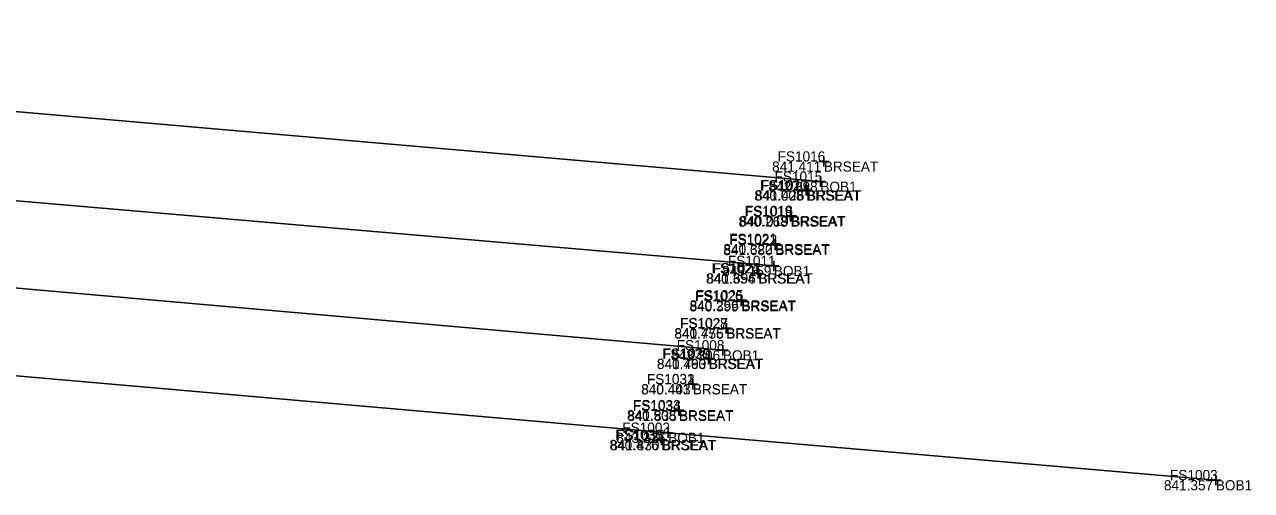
# Model space of a CAD drawing. Extents: x 1455931 to 1456172, y 560190 to 560355.
# Drawn here: x 1456051.6 to 1456172.2, y 560192.7 to 560238.5 of the extents above; entities that cross this region are included whole.
import ezdxf

# ---------------------------------------------------------------- set-up
doc = ezdxf.new("R2010")
doc.units = 0
for name, color, linetype in [('BR_X_SV_Beam_Seat', 7, 'Continuous'), ('BR_X_SV_Bottom_of_Beam', 7, 'Continuous'), ('BR_X_SV_Bottom_of_Beam_Text', 7, 'Continuous'), ('BR_X_SV_Shot_Marker', 7, 'Continuous'), ('SV_X_Shot_Marker', 7, 'Continuous')]:
    doc.layers.add(name, color=color, linetype=linetype)

msp = doc.modelspace()

# ---------------------------------------------------------------- linework, layer by layer
at = {"layer": 'BR_X_SV_Bottom_of_Beam'}
for points in [[(1455951.93, 560238.47), (1455951.93, 560238.47), (1456040.42, 560230.81), (1456129.8, 560223.03)], [(1455947.04, 560230.18), (1456035.55, 560222.47), (1456125.23, 560214.75)], [(1455942.3, 560222.35), (1456030.42, 560214.36), (1456120.23, 560206.46)], [(1455937.5, 560213.52), (1456026.06, 560206.1), (1456114.85, 560198.36), (1456168.66, 560193.7)]]:
    msp.add_lwpolyline(points, dxfattribs=at)
at = {"layer": 'BR_X_SV_Shot_Marker'}
for p, q in [((1456129.64, 560225.01), (1456130.64, 560225.01)), ((1456130.14, 560225.51), (1456130.14, 560224.51)), ((1456130.14, 560225.01), (1456130.14, 560225.01)), ((1456128.42, 560222.66), (1456128.42, 560221.66)), ((1456128.5, 560222.69), (1456128.5, 560221.69)), ((1456127.92, 560222.16), (1456128.92, 560222.16)), ((1456128, 560222.19), (1456129, 560222.19)), ((1456128.42, 560222.16), (1456128.42, 560222.16)), ((1456128.5, 560222.19), (1456128.5, 560222.19)), ((1456126.87, 560220.1), (1456126.87, 560219.1)), ((1456126.95, 560220.16), (1456126.95, 560219.16)), ((1456126.37, 560219.6), (1456127.37, 560219.6)), ((1456126.45, 560219.66), (1456127.45, 560219.66)), ((1456126.87, 560219.6), (1456126.87, 560219.6)), ((1456126.95, 560219.66), (1456126.95, 560219.66)), ((1456124.86, 560216.91), (1456125.86, 560216.91)), ((1456124.88, 560216.81), (1456125.88, 560216.81)), ((1456125.36, 560217.41), (1456125.36, 560216.41)), ((1456125.36, 560216.91), (1456125.36, 560216.91)), ((1456125.38, 560217.31), (1456125.38, 560216.31)), ((1456125.38, 560216.81), (1456125.38, 560216.81)), ((1456123.18, 560214.02), (1456124.18, 560214.02)), ((1456123.23, 560214.02), (1456124.23, 560214.02)), ((1456123.68, 560214.52), (1456123.68, 560213.52)), ((1456123.68, 560214.02), (1456123.68, 560214.02)), ((1456123.73, 560214.52), (1456123.73, 560213.52)), ((1456123.73, 560214.02), (1456123.73, 560214.02)), ((1456122.02, 560211.78), (1456122.02, 560210.78)), ((1456122.07, 560211.87), (1456122.07, 560210.87)), ((1456121.52, 560211.28), (1456122.52, 560211.28)), ((1456121.57, 560211.37), (1456122.57, 560211.37)), ((1456122.02, 560211.28), (1456122.02, 560211.28)), ((1456122.07, 560211.37), (1456122.07, 560211.37)), ((1456120.54, 560209.1), (1456120.54, 560208.1)), ((1456120.57, 560209.14), (1456120.57, 560208.14)), ((1456120.04, 560208.6), (1456121.04, 560208.6)), ((1456120.07, 560208.64), (1456121.07, 560208.64)), ((1456120.54, 560208.6), (1456120.54, 560208.6)), ((1456120.57, 560208.64), (1456120.57, 560208.64)), ((1456118.3, 560205.61), (1456119.3, 560205.61)), ((1456118.36, 560205.64), (1456119.36, 560205.64)), ((1456118.8, 560206.11), (1456118.8, 560205.11)), ((1456118.8, 560205.61), (1456118.8, 560205.61)), ((1456118.86, 560206.14), (1456118.86, 560205.14)), ((1456118.86, 560205.64), (1456118.86, 560205.64)), ((1456116.77, 560203.14), (1456117.77, 560203.14)), ((1456116.77, 560203.12), (1456117.77, 560203.12)), ((1456117.27, 560203.64), (1456117.27, 560202.64)), ((1456117.27, 560203.62), (1456117.27, 560202.62)), ((1456117.27, 560203.14), (1456117.27, 560203.14)), ((1456117.27, 560203.12), (1456117.27, 560203.12)), ((1456115.4, 560200.58), (1456116.4, 560200.58)), ((1456115.9, 560201.08), (1456115.9, 560200.08)), ((1456115.9, 560200.58), (1456115.9, 560200.58)), ((1456115.92, 560201.01), (1456115.92, 560200.01)), ((1456115.42, 560200.51), (1456116.42, 560200.51)), ((1456115.92, 560200.51), (1456115.92, 560200.51)), ((1456114.18, 560198.16), (1456114.18, 560197.16)), ((1456113.68, 560197.66), (1456114.68, 560197.66)), ((1456113.76, 560197.63), (1456114.76, 560197.63)), ((1456114.18, 560197.66), (1456114.18, 560197.66)), ((1456114.26, 560198.13), (1456114.26, 560197.13)), ((1456114.26, 560197.63), (1456114.26, 560197.63))]:
    msp.add_line(p, q, dxfattribs=at)
at = {"layer": 'SV_X_Shot_Marker'}
for p, q in [((1456129.8, 560223.53), (1456129.8, 560222.53)), ((1456129.3, 560223.03), (1456130.3, 560223.03)), ((1456129.8, 560223.03), (1456129.8, 560223.03)), ((1456125.23, 560215.25), (1456125.23, 560214.25)), ((1456124.73, 560214.75), (1456125.73, 560214.75)), ((1456125.23, 560214.75), (1456125.23, 560214.75)), ((1456120.23, 560206.96), (1456120.23, 560205.96)), ((1456119.73, 560206.46), (1456120.73, 560206.46)), ((1456120.23, 560206.46), (1456120.23, 560206.46)), ((1456114.35, 560198.36), (1456115.35, 560198.36)), ((1456114.85, 560198.86), (1456114.85, 560197.86)), ((1456114.85, 560198.36), (1456114.85, 560198.36)), ((1456168.16, 560193.7), (1456169.16, 560193.7)), ((1456168.66, 560194.2), (1456168.66, 560193.2)), ((1456168.66, 560193.7), (1456168.66, 560193.7))]:
    msp.add_line(p, q, dxfattribs=at)

# ---------------------------------------------------------------- texts
at = {"layer": 'BR_X_SV_Beam_Seat'}
for s, p in [('FS1016', (1456125.6, 560225.01)), ('841.411', (1456125.06, 560224.01)), ('BRSEAT', (1456130.14, 560224.01)), ('FS1020', (1456123.87, 560222.16)), ('FS1017', (1456123.97, 560222.19)), ('840.008', (1456123.31, 560221.16)), ('841.426', (1456123.39, 560221.19)), ('BRSEAT', (1456128.42, 560221.16)), ('BRSEAT', (1456128.5, 560221.19)), ('FS1019', (1456122.35, 560219.6)), ('FS1018', (1456122.41, 560219.66)), ('840.268', (1456121.76, 560218.6)), ('840.019', (1456121.86, 560218.66)), ('BRSEAT', (1456126.87, 560218.6)), ('BRSEAT', (1456126.95, 560218.66)), ('FS1021', (1456120.84, 560216.91)), ('FS1022', (1456120.87, 560216.81)), ('841.680', (1456120.27, 560215.81)), ('840.322', (1456120.28, 560215.91)), ('BRSEAT', (1456125.36, 560215.91)), ('BRSEAT', (1456125.38, 560215.81)), ('FS1024', (1456119.12, 560214.02)), ('FS1023', (1456119.23, 560214.02)), ('840.354', (1456118.56, 560213.02)), ('841.696', (1456118.62, 560213.02)), ('BRSEAT', (1456123.68, 560213.02)), ('BRSEAT', (1456123.73, 560213.02)), ('FS1026', (1456117.48, 560211.28)), ('FS1025', (1456117.56, 560211.37)), ('840.399', (1456116.94, 560210.28)), ('840.256', (1456116.96, 560210.37)), ('BRSEAT', (1456122.02, 560210.28)), ('BRSEAT', (1456122.07, 560210.37)), ('FS1028', (1456116, 560208.6)), ('FS1027', (1456116.04, 560208.64)), ('840.476', (1456115.46, 560207.64)), ('841.755', (1456115.47, 560207.6)), ('BRSEAT', (1456120.54, 560207.6)), ('BRSEAT', (1456120.57, 560207.64)), ('FS1030', (1456114.25, 560205.61)), ('FS1029', (1456114.34, 560205.64)), ('840.463', (1456113.74, 560204.61)), ('841.790', (1456113.74, 560204.64)), ('BRSEAT', (1456118.8, 560204.61)), ('BRSEAT', (1456118.86, 560204.64)), ('840.441', (1456112.19, 560202.12)), ('840.403', (1456112.21, 560202.14)), ('FS1031', (1456112.76, 560203.14)), ('FS1032', (1456112.76, 560203.12)), ('BRSEAT', (1456117.27, 560202.14)), ('BRSEAT', (1456117.27, 560202.12)), ('840.508', (1456110.8, 560199.58)), ('FS1034', (1456111.37, 560200.51)), ('FS1033', (1456111.4, 560200.58)), ('BRSEAT', (1456115.9, 560199.58)), ('841.835', (1456110.85, 560199.51)), ('BRSEAT', (1456115.92, 560199.51)), ('FS1036', (1456109.64, 560197.66)), ('FS1035', (1456109.75, 560197.63)), ('840.476', (1456109.08, 560196.66)), ('841.830', (1456109.15, 560196.63)), ('BRSEAT', (1456114.18, 560196.66)), ('BRSEAT', (1456114.26, 560196.63))]:
    msp.add_text(s, height=1, dxfattribs=at).set_placement(p)
at = {"layer": 'BR_X_SV_Bottom_of_Beam_Text'}
for s, p in [('FS1015', (1456125.3, 560223.03)), ('842.898', (1456124.7, 560222.03)), ('BOB1', (1456129.8, 560222.03)), ('FS1011', (1456120.72, 560214.75)), ('843.159', (1456120.15, 560213.75)), ('BOB1', (1456125.23, 560213.75)), ('FS1008', (1456115.69, 560206.46)), ('843.306', (1456115.12, 560205.46)), ('BOB1', (1456120.23, 560205.46)), ('FS1002', (1456110.34, 560198.36)), ('843.326', (1456109.75, 560197.36)), ('BOB1', (1456114.85, 560197.36)), ('FS1003', (1456164.16, 560193.7)), ('841.357', (1456163.56, 560192.7)), ('BOB1', (1456168.66, 560192.7))]:
    msp.add_text(s, height=1, dxfattribs=at).set_placement(p)

doc.saveas('drawing.dxf')
